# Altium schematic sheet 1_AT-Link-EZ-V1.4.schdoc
size 309 x 223 mm; Symbol: Artery_A4; Device: Artery_A4; @Project Name: AT-START-M412; @Page Count: 4; @Create Date: 2024-06-20; Company: Artery Technology; Drawed: SD; Version: 1.0; Page Size: A4; @Update Date: 2024-08-05; @Page No: 1; @Schematic Name: AT-START-M412-V1.0; @Page Name: AT-Link-EZ-V1.4; @Board Name: AT-START-M412-V1.0; @Create Time: 16:55:15; @Update Time: 13:09:32
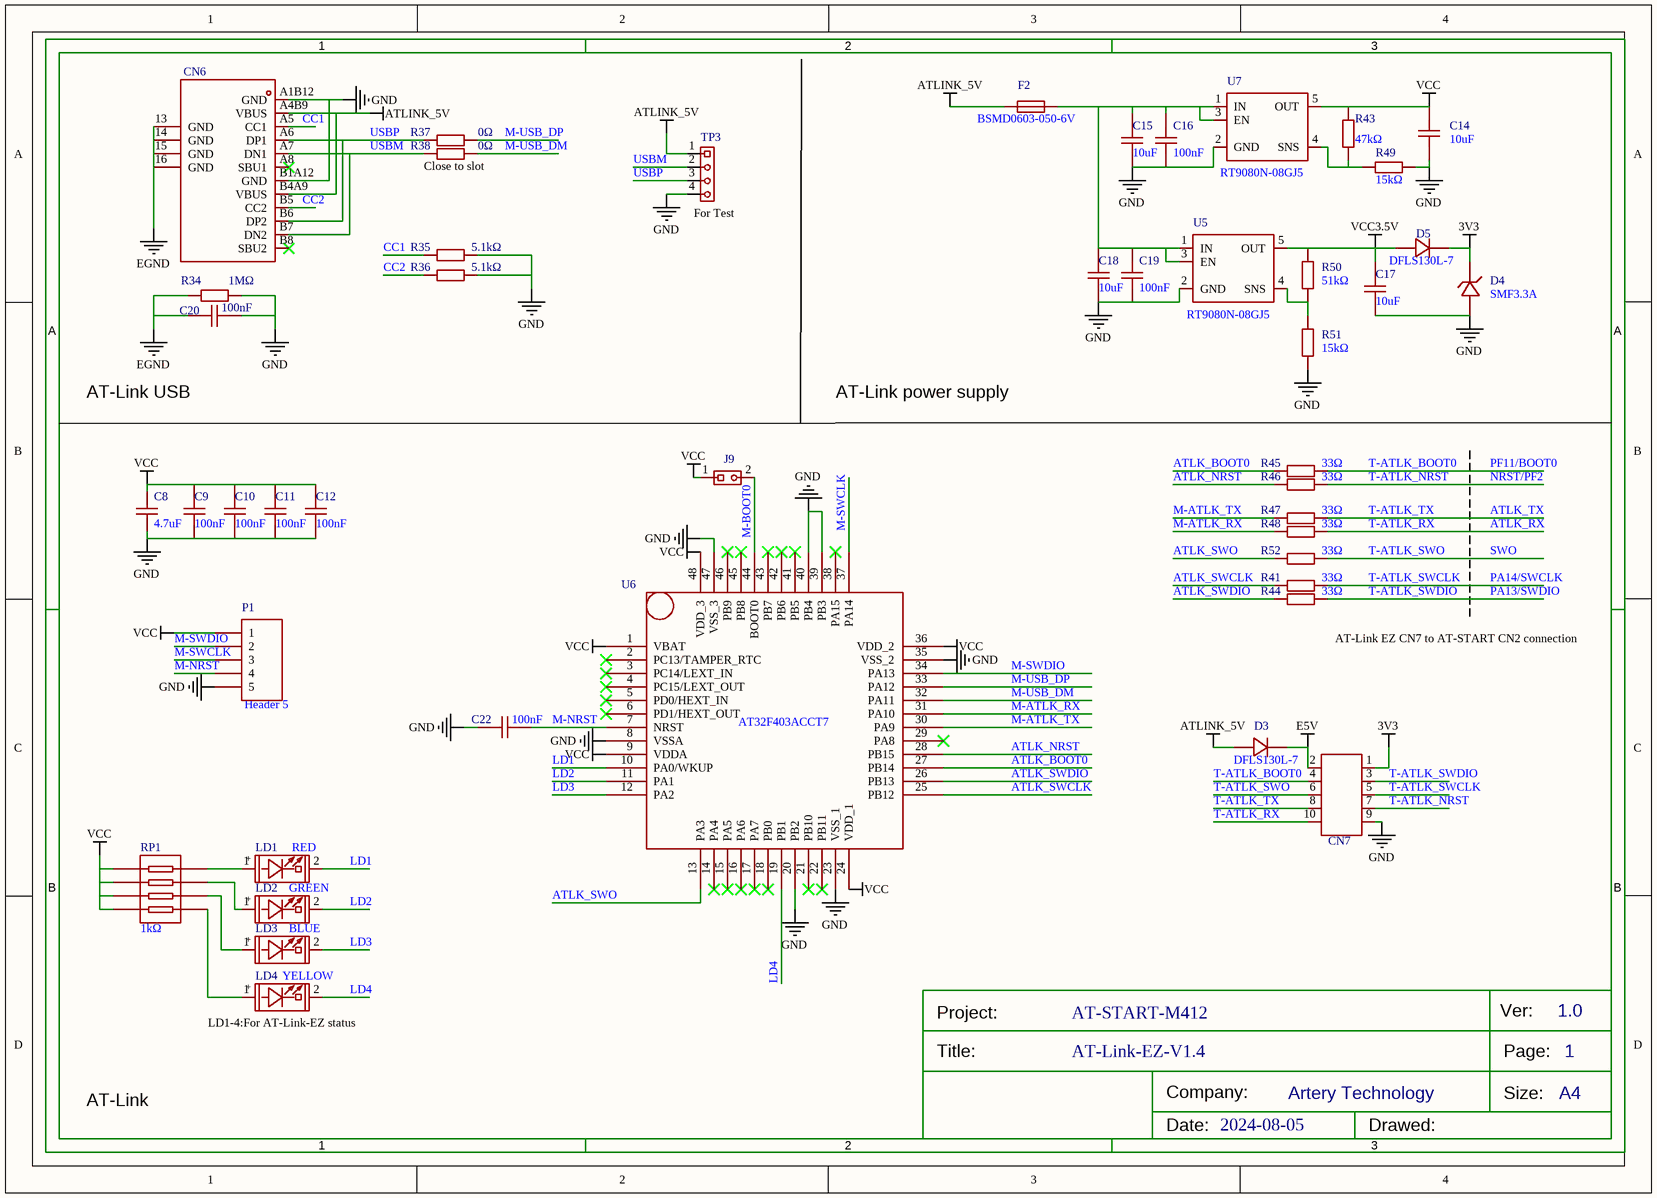
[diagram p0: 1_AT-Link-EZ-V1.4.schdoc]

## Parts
C8  4.7uF  [C0603]  (value not drawn)
C9  100nF  [C0603]  (value not drawn)
C10  100nF  [C0603]  (value not drawn)
C11  100nF  [C0603]  (value not drawn)
C12  100nF  [C0603]  (value not drawn)
C14  10uF  [C0603]  (value not drawn)
C15  10uF  [C0603]  (value not drawn)
C16  100nF  [C0603]  (value not drawn)
C17  10uF  [C0603]  (value not drawn)
C18  10uF  [C0603]  (value not drawn)
C19  100nF  [C0603]  (value not drawn)
C20  value 100nF  [C0603]  (hidden comment: CC0603KRX7R9BB104)
C22  100nF  [C0603]  (value not drawn)
CN6  TYPEC-304-BCP16  [USB-C-SMD_TYPEC-304-BCP16]  (value not drawn)
CN7  CON10  [HDR2X5]  (value not drawn)
D3  DFLS130L-7  [POWERDI-123_L2.8-W1.8-LS3.7-RD]  (value not drawn)
D4  SMF3.3A  [SOD-123FL_L2.8-W1.8-LS3.8-RD]  (value not drawn)
D5  DFLS130L-7  [POWERDI-123_L2.8-W1.8-LS3.7-RD]  (value not drawn)
F2  BSMD0603-050-6V  [F0603]  (value not drawn)
J9  1X2P_2.54M  [HDR1X2]  (value not drawn)
LD1  RED  [LED0603]  (value not drawn)
LD2  GREEN  [LED0603]  (value not drawn)
LD3  BLUE  [LED0603]  (value not drawn)
LD4  YELLOW  [LED0603]  (value not drawn)
P1  Header 5  [HDR1X5]  (value not drawn)
R34  value 1MΩ  [R0603]  (hidden comment: RC0603FR-071ML)
R35  value 5.1kΩ  [R0603]  (hidden comment: 0603WAF5101T5E)
R36  value 5.1kΩ  [R0603]  (hidden comment: 0603WAF5101T5E)
R37  value 0Ω  [R0603]  (hidden comment: 0603WAF0000T5E)
R38  value 0Ω  [R0603]  (hidden comment: 0603WAF0000T5E)
R41  33Ω  [R0603]  (value not drawn)
R43  47kΩ  [R0603]  (value not drawn)
R44  33Ω  [R0603]  (value not drawn)
R45  33Ω  [R0603]  (value not drawn)
R46  33Ω  [R0603]  (value not drawn)
R47  33Ω  [R0603]  (value not drawn)
R48  33Ω  [R0603]  (value not drawn)
R49  15kΩ  [R0603]  (value not drawn)
R50  51kΩ  [R0603]  (value not drawn)
R51  15kΩ  [R0603]  (value not drawn)
R52  33Ω  [R0603]  (value not drawn)
RP1  1kΩ  [RES-ARRAY-SMD_0603-8P-L3.2-W1.6-BL]  (value not drawn)
TP3  1X4P_2.54F  [HDR1X4 - TOP]  (value not drawn)
U5  RT9080N-08GJ5  [SOT-23-5]  (value not drawn)
U6  AT32F403ACCT7  [LQFP48 - 2]  (value not drawn)
U7  RT9080N-08GJ5  [SOT-23-5]  (value not drawn)

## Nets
3V3: CN7.1 D4.1(C) D5.1
ATLINK_5V: CN6.A4B9(VBUS) CN6.B4A9(VBUS) D3.2 F2.1 TP3.1
E5V: CN7.2 D3.1
EGND: C20.2 CN6.13(GND) CN6.14(GND) CN6.15(GND) CN6.16(GND) R34.1
GND: C8.1 C9.1 C10.1 C11.1 C12.1 C14.1 C15.1 C16.1 C17.1 C18.1 C19.1 C20.1 C22.1 CN6.A1B12(GND) CN6.B1A12(GND) CN7.9 D4.2(A) P1.5 R34.2 R35.2 R36.2 R49.2 R51.2 TP3.4 U5.2(GND) U6.8(VSSA) U6.20(PB2) U6.23(VSS_1) U6.35(VSS_2) U6.39(PB3) U6.40(PB4) U6.47(VSS_3) U7.2(GND)
VCC: C8.2 C9.2 C10.2 C11.2 C12.2 C14.2 J9.1 P1.1 R43.1 RP1.1 RP1.2 RP1.3 RP1.4 U6.1(VBAT) U6.9(VDDA) U6.24(VDD_1) U6.36(VDD_2) U6.48(VDD_3) U7.5(OUT)
VCC3.5V: C17.2 D5.2 R50.1 U5.5(OUT)
ATLK_BOOT0: R45.1 U6.27(PB14)
ATLK_NRST: R46.1 U6.28(PB15)
ATLK_RX: CN7.10 R48.2  [also labelled T-ATLK_RX]
ATLK_SWCLK: R41.1 U6.25(PB12)
ATLK_SWDIO: R44.1 U6.26(PB13)
ATLK_SWO: R52.1 U6.13(PA3)
ATLK_TX: CN7.8 R47.2  [also labelled T-ATLK_TX]
CC1: CN6.A5(CC1) R35.1
CC2: CN6.B5(CC2) R36.1
LD1: LD1.2(CATHODE) U6.10(PA0/WKUP)
LD2: LD2.2(CATHODE) U6.11(PA1)
LD3: LD3.2(CATHODE) U6.12(PA2)
LD4: LD4.2(CATHODE) U6.19(PB1)
M-ATLK_RX: R48.1 U6.31(PA10)
M-ATLK_TX: R47.1 U6.30(PA9)
M-BOOT0: J9.2 U6.44(BOOT0)
M-NRST: C22.2 P1.4 U6.7(NRST)
M-SWCLK: P1.3 U6.37(PA14)
M-SWDIO: P1.2 U6.34(PA13)
M-USB_DM: R38.2 U6.32(PA11)
M-USB_DP: R37.2 U6.33(PA12)
NRST/PF2: CN7.7 R46.2  [also labelled T-ATLK_NRST]
PA13/SWDIO: CN7.3 R44.2  [also labelled T-ATLK_SWDIO]
PA14/SWCLK: CN7.5 R41.2  [also labelled T-ATLK_SWCLK]
PF11/BOOT0: CN7.4 R45.2  [also labelled T-ATLK_BOOT0]
SWO: CN7.6 R52.2  [also labelled T-ATLK_SWO]
USBM: CN6.A7(DN1) CN6.B7(DN2) R38.1 TP3.2
USBP: CN6.A6(DP1) CN6.B6(DP2) R37.1 TP3.3
NetC15_2: C15.2 C16.2 C18.2 C19.2 F2.2 U5.1(IN) U5.3(EN) U7.1(IN) U7.3(EN)
NetLD1_1: LD1.1(ANODE) RP1.8
NetLD2_1: LD2.1(ANODE) RP1.7
NetLD3_1: LD3.1(ANODE) RP1.6
NetLD4_1: LD4.1(ANODE) RP1.5
NetR43_2: R43.2 R49.1 U7.4(SNS)
NetR50_2: R50.2 R51.1 U5.4(SNS)

Not connected (* = marked no-connect by the designer): CN6 A8(SBU1)* B8(SBU2)*; U6 2(PC13/TAMPER_RTC)* 3(PC14/LEXT_IN)* 4(PC15/LEXT_OUT)* 5(PD0/HEXT_IN)* 6(PD1/HEXT_OUT)* 14(PA4)* 15(PA5)* 16(PA6)* 17(PA7)* 18(PB0)* 21(PB10)* 22(PB11)* 29(PA8)* 38(PA15)* 41(PB5)* 42(PB6)* 43(PB7)* 45(PB8)* 46(PB9)*

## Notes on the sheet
- (near R38) Close to slot
- (near TP3) For Test
- AT-Link USB
- AT-Link power supply
- AT-Link EZ CN7 to AT-START CN2 connection
- (near LD4) LD1-4:For AT-Link-EZ status
- AT-START-M412
- AT-Link
- 2024-08-05

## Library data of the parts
C8 = CL10A475KO8NNNC: 容值:4.7uF;精度:±10%;额定电压:16V;材质(温度系数):X5R;; Manufacturer: SAMSUNG(三星); Add into BOM: yes; Tolerance: ±10%; Voltage Rated: 16V; Temperature Coefficient: X5R; Origin Footprint 2: 0603; Origin Footprint 3: 0402; Origin Footprint 4: C2512; Origin Footprint 5: 1608[0603]; Origin Footprint 6: C1210
C9-C12 = CC0603KRX7R9BB104: 容值:100nF;精度:±10%;额定电压:50V;材质(温度系数):X7R;; Manufacturer: YAGEO(国巨); Add into BOM: yes; Tolerance: ±10%; Voltage Rated: 50V; Temperature Coefficient: X7R; Origin Footprint 2: 0603; Origin Footprint 3: 0402; Origin Footprint 4: C2512; Origin Footprint 5: 1608[0603]; Origin Footprint 6: C1210
C14 C15 C17 C18 = CL10A106KP8NNNC: 容值:10uF;精度:±10%;额定电压:10V;材质(温度系数):X5R;; Manufacturer: SAMSUNG(三星); Add into BOM: yes; Tolerance: ±10%; Voltage Rated: 10V; Temperature Coefficient: X5R
C16 C19 C22 = CC0603KRX7R9BB104: 容值:100nF;精度:±10%;额定电压:50V;材质(温度系数):X7R;; Manufacturer: YAGEO(国巨); Add into BOM: yes; Tolerance: ±10%; Voltage Rated: 50V; Temperature Coefficient: X7R
C20 = CC0603KRX7R9BB104: 容值:100nF;精度:±10%;额定电压:50V;温度系数:X7R;; Manufacturer: YAGEO(国巨); Add into BOM: yes; Tolerance: ±10%; Voltage Rated: 50V; Temperature Coefficient: X7R
CN6 = TYPEC-304-BCP16: 连接器类型:Type-C;标准:USB 3.1;公母:母座;触点数量:16.0;端口数量:1;安装方式:卧贴;额定电流 - 电源:3A;工作温度范围:-25~+85;焊接温度(最大值):260;; Manufacturer: XUNPU(讯普); Add into BOM: yes; Connector Type: Type-C; Gender: 母座; Number of Contacts: 16.0; Number of Ports: 1; Mounting Sytle: 卧贴; Current Rating - Power (Max): 3A; Welding Temperature (Max): 260
CN7 = CON10: 简易牛角DC3-10P 双排90度弯插针 2.54mm 2*5P双排 黑色; Symbol: CON10A_0; Add into BOM: yes
D3 D5 = DFLS130L-7: 正向压降(Vf):310mV@1A;直流反向耐压(Vr):30V;平均整流电流(Io):1A;; Manufacturer: DIODES(美台); Add into BOM: yes; Reverse Voltage (Vr): 30V; Average Rectified Current (Io): 1A; Origin Footprint: SOD-123
D4 = SMF3.3A_C2759873: 反向截止电压(Vrwm):3.3V;最大钳位电压:7.3V;峰值脉冲电流(Ipp)@10/1000us:27.5A;击穿电压:4.1V;; Manufacturer: Leiditech(雷卯电子); Add into BOM: yes; Reverse Stand-Off Voltage (Vrwm): 3.3V; Maximum Clamping Voltage: 7.3V; Peak Pulse Current (Ipp)@10/1000us: 27.5A; Breakdown Voltage: 4.1V; Reverse Leakage Current (Ir): 500uA; Type: TVS; Origin Footprint: SOD-123
F2 = BSMD0603-050-6V: 最大电压:6V;最大电流:40A;保持电流:500mA;跳闸电流:1A;; Manufacturer: BHFUSE(佰宏); Add into BOM: yes; Operating Voltage (Max): 6V; Current Rating (Max): 40A; Hold Current: 500mA; Trip Current: 1A; Power Dissipation: 500mW; Resistance - Initial (Ri) (Min): 100mΩ; Resistance - Post Trip (R1) (Max): 800mΩ; Maximum Time to Trip: 100ms; Origin Footprint: r0603
J9 = 1X2P_2.54M: 单排直插针1*2P 2.54mm（黑色）; Symbol: 1X2P,Male,DIP_2.54; Origin Footprint 2: SIP_2P; Add into BOM: yes; Check: true
LD1 = RED: 贴片LED 红色  0603; Symbol: RED,SMD0603; Add into BOM: yes
LD2 = GREEN: 贴片LED 绿色 0603; Symbol: GREEN,SMD0603; Add into BOM: yes
LD3 = BLUE: 贴片LED 蓝色 0603; Symbol: BLUE,SMD0603; Add into BOM: yes
LD4 = YELLOW: 贴片LED 黄色 0603; Symbol: YELLOW,SMD0603; Add into BOM: yes
P1 = Header 5: 单排直插针1*5P 2.54mm （黑色）; Add into BOM: yes
R34 = RC0603FR-071ML: 阻值:1MΩ;精度:±1%;功率:100mW;温度系数:±100ppm/;最大工作电压:75V;工作温度范围:-55~+155;; Manufacturer: YAGEO(国巨); Add into BOM: yes; Tolerance: ±1%; Power(Watts): 100mW; Overload Voltage (Max): 75V
R35 R36 = 0603WAF5101T5E: 电阻类型:厚膜电阻;阻值:5.1kΩ;精度:±1%;功率:1/10W;温度系数:±100ppm/;最大工作电压:75V;工作温度范围:-55~+155;; Manufacturer: UNI-ROYAL(厚声); Add into BOM: yes; Tolerance: ±1%; Power(Watts): 1/10W; Overload Voltage (Max): 75V
R37 R38 = 0603WAF0000T5E: 电阻类型:厚膜电阻;阻值:0Ω;精度:±1%;功率:1/10W;温度系数:-;最大工作电压:75V;工作温度范围:-55~+155;; Manufacturer: UNI-ROYAL(厚声); Add into BOM: yes; Tolerance: ±1%; Power(Watts): 1/10W; Overload Voltage (Max): 75V
R41 R44-R48 R52 = 0603WAF330JT5E: 电阻类型:厚膜电阻;阻值:33Ω;精度:±1%;功率:100mW;最大工作电压:75V;温度系数:±100ppm/℃;; Manufacturer: UNI-ROYAL(厚声); Add into BOM: yes; Tolerance: ±1%; Power(Watts): 100mW; Overload Voltage (Max): 75V
R43 = 0603WAF4702T5E: 电阻类型:厚膜电阻;阻值:47kΩ;精度:±1%;功率:100mW;最大工作电压:75V;温度系数:±100ppm/℃;; Manufacturer: UNI-ROYAL(厚声); Add into BOM: yes; Tolerance: ±1%; Power(Watts): 100mW; Overload Voltage (Max): 75V
R49 R51 = 0603WAF1502T5E: 电阻类型:厚膜电阻;阻值:15kΩ;精度:±1%;功率:100mW;最大工作电压:75V;温度系数:±100ppm/℃;; Manufacturer: UNI-ROYAL(厚声); Add into BOM: yes; Tolerance: ±1%; Power(Watts): 100mW; Overload Voltage (Max): 75V
R50 = 0603WAF5102T5E: 电阻类型:厚膜电阻;阻值:51kΩ;精度:±1%;功率:100mW;最大工作电压:75V;温度系数:±100ppm/℃;; Manufacturer: UNI-ROYAL(厚声); Add into BOM: yes; Tolerance: ±1%; Power(Watts): 100mW; Overload Voltage (Max): 75V
RP1 = 4D03WGJ0102T5E: 电阻器数:4;阻值:1kΩ;精度:±5%;单个元件功率:62.5mW;温度系数:±200ppm/℃;; Manufacturer: UNI-ROYAL(厚声); Add into BOM: yes; Number of Resistors: 4; Tolerance: ±5%; Power(Watts): 62.5mW; Origin Footprint: RP_4-0603
TP3 = 1X4P_2.54F: Convert to PCB: yes
U5 U7 = RT9080N-08GJ5: Add into BOM: yes
U6 = AT32F403CGT6: Symbol: LQFP48&QFN48; Add into BOM: yes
